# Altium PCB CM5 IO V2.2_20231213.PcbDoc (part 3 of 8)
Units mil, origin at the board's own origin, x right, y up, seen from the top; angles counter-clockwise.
Board outline 6299.61 x 3544.09 mil, 4 copper layers (Top, GND, Power, Bottom), stack 35.4 mil thick; 482 components, 404 nets, 1857 pads, 2731 vias.
Unrouted connection lines stored in the file: 1872.
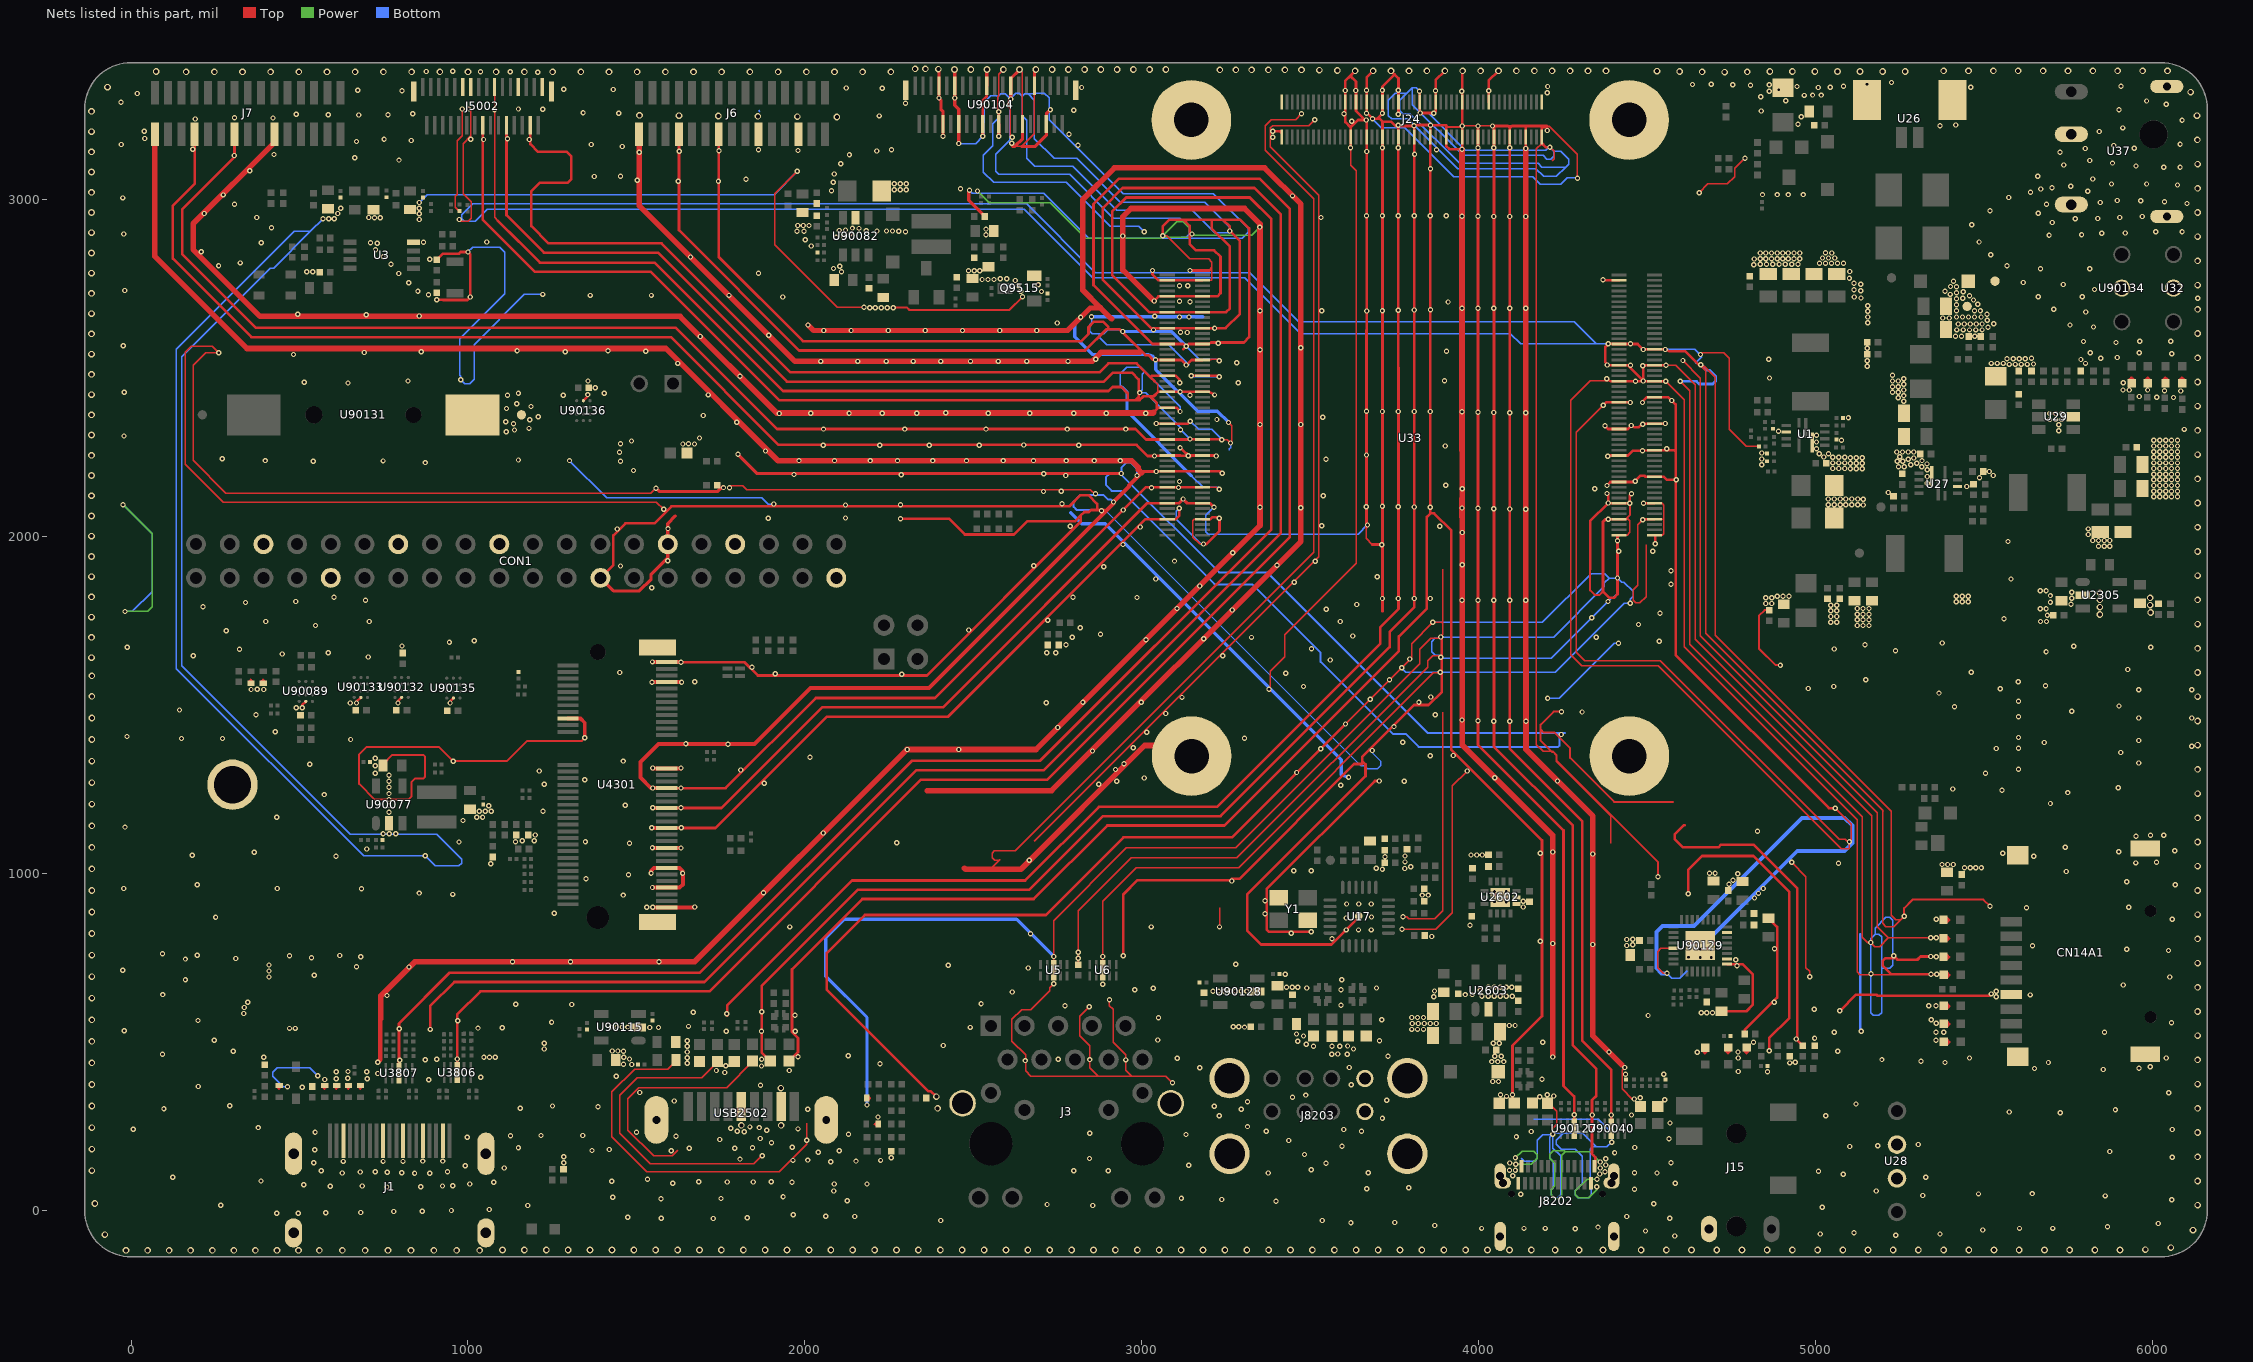
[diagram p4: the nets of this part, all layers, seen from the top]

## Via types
v1: diameter 15.75, hole 7.87, Top to Bottom, 2292 vias
v2: diameter 19.68, hole 11.81, Top to Bottom, 439 vias

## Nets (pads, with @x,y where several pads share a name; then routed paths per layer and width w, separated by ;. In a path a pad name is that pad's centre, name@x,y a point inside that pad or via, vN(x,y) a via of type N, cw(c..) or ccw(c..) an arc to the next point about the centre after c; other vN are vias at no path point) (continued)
GND: C1.2 C3.1 C4.2 C5.2 C34.2 C83.1 C84.2 C85.2 C87.2 C88.2 C89.2 C126.1 C127.1 C130.2 C131.2 C132.2 C133.2 C134.2 C135.2 C136.2 C137.2 C138.2 C139.2 C140.2 C141.2 C142.2 C143.2 C144.2 C146.2 C147.2 C149.2 C150.2 C151.1 C152.2 C153.2 C154.2 C155.2 C156.2 C265.2 C267.2 C268.2 C269.2 C548.2 C549.2 C558.2 C559.2 C561.2 C562.2 C563.2 C564.2 C565.2 C569.2 C570.2 C571.2 C572.2 C573.2 C574.2 C658.2 C750.1 C812.2 C813.2 C2282.2 C2283.2 C2284.2 C2330.2 C2332.2 C2335.2 C2606.2 C2607.2 C2608.2 C2609.2 C2611.2 C2612.2 C2613.2 C2614.2 C7320.2 C7322.2 C90084.2 C90399.2 C90408.2 C90409.2 C90410.2 C90431.2 C90448.2 C90478.2 C90479.2 C90480.2 C90482.2 C90483.2 C90484.2 C90485.2 C90486.2 C90487.2 C90488.2 C90490.2 C90582.1 C90615.2 C90616.2 C90617.2 C90618.1 C90750.2 C90751.2 C90772.2 C90773.2 C90774.2 C90775.2 C90776.2 C90777.2 C90778.2 C90779.2 C90780.2 C90781.2 C90782.1 C90783.1 C90784.1 C90787.1 C90788.1 C90789.2 C90790.2 CN14A1.6 CN14A1.10 CN14A1.11 CN14A1.12 CN14A1.13 CON1.6 CON1.9 CON1.14 CON1.20 CON1.25 CON1.30 CON1.34 CON1.39 D3.1 D4.1 D41.1 D47.1 D48.1 D49.1 D90031.2 D90032.2 D90033.2 D90034.2 D90035.2 D90037.2 ED1.2 ED2.2 ED3.2 ED5.2 ED6.2 ED9.2 ED10.2 ED11.2 ED12.2 ED13.2 ED14.2 ED15.2 ED20.2 ED21.2 ED22.2 ED2109.2 ED2110.2 ED2111.2 ED4806.2 ED7104.2 ED9203.2 ED9204.2 ED9205.2 ED9206.2 ESD2701.2 ESD2702.2 ESD2703.2 ESD2704.2 ESD2706.2 ESD27052.2 J1.2 J1.5 J1.8 J1.11 J1.17 J1.20 J1.21 J1.22 J1.23 J2.1 J3.19 J3.20 J6.3 J6.6 J6.9 J6.12 J6.15 J7.6 J7.9 J7.12 J7.15 J15.2 J24.1 J24.2 J24.7 J24.13 J24.19 J24.22 J24.25 J24.31 J24.32 J24.37 J24.42 J24.43 J24.48 J24.49 J24.55 J24.56 J24.61 J24.62 J24.67 J24.68 J24.72 J24.73 J24.76 J24.99 J24.100 J5002.1 J5002.4 J5002.7 J5002.10 J5002.13 J5002.16 J5002.19 J5002.21 J5002.32 J5002.33 J8202.A1 J8202.A12 J8202.B1 J8202.B12 J8202.E1 J8202.E2 J8202.E3 J8202.E4 J8202.E5 J8202.E6 J8203.4 J8203.8 J8203.9 J8203.10 J8203.11 J8203.12 P6.1 Q9515.2 R1.1 R7.1 R97.1 R102.2 R152.1 R154.1 R160.2 R161.2 R353.2 R2005.2 R2006.2 R2322.2 R2611.2 R2612.2 R5004.2 R7125.2 R7315.1 R90338.1 R91193.2 R95043.2 R95114.1 R95116.2 R95117.2 R95159.2 R95210.2 R95555.2 R95556.2 R95578.1 R95579.2 R95598.2 R95602.2 R95606.1 R95614.2 R95615.2 TP11.1 TP14.1 U1.2 U1.10 U3.4 U5.3 U5.8 U6.3 U6.8 U17.25 U26.3 U26.4 U27.2 U27.10 U28.2 U28.3 U29.2 U32.2 U33.1 U33.2 U33.7 U33.8 U33.13 U33.14 U33.22 U33.23 U33.32 U33.33 U33.42 U33.43 U33.52 U33.53 U33.59 U33.60 U33.65 U33.66 U33.71 U33.74 U33.98 U33.107 U33.108 U33.113 U33.114 U33.119 U33.120 U33.125 U33.126 U33.131 U33.132 U33.137 U33.138 U33.144 U33.150 U33.155 U33.156 U33.161 U33.162 U33.167 U33.168 U33.173 U33.174 U33.179 U33.180 U33.185 U33.186 U33.191 U33.192 U33.197 U33.198 U33.201 U33.202 U33.203 U33.204 U37.2 U37.3 U37.4 U37.5 U2305.2 U2602.8 U2602.9 U2602.15 U2603.2 U3806.3 U3806.8 U3807.3 U3807.8 U4301.1 U4301.7 U4301.18 U4301.33 U4301.39 U4301.45 U4301.51 U4301.57 U4301.63 U4301.69 U4301.75 U4301.76 U4301.77 U90040.3 U90040.8 U90077.2 U90082.2 U90089.D2 U90104.6 U90104.9 U90104.12 U90104.15 U90104.18 U90104.21 U90104.22 U90104.28 U90104.29 U90104.32 U90104.33 U90104.40 U90104.41 U90115.2 U90127.3 U90127.8 U90128.2 U90129.5 U90129.17 U90129.18 U90129.23 U90129.33 U90131.2 U90132.D2 U90133.D2 U90134.2 U90135.D2 U90136.D2 USB2502.4 USB2502.7 USB2502.10 USB2502.11 Y1.2 Y1.4 | length 218612.2
  Top w3.94: v1(974.41,2939.96) 980.31,2934.06 1000.79,2934.06 1009.84,2943.11 1009.84,2992.13 985.24,3016.73 985.24,3165.05 1008.78,3188.59 1008.78,3191.93 1008.78,3261.89 v1(1002.95,3267.72) ; C750.1@974.41,2964.57 966.54,2972.44 966.06,2972.44 962.6,2975.9 962.6,3008.85 968.51,3014.76 968.51,3174.22 983.35,3189.06 983.35,3252.59 983.27,3252.67 v1(983.27,3267.72) ; J5002.13@1078.74,3332.68 1078.74,2945.86 1088.58,2936.02 ; v1(1557.85,2142.26) 1542.56,2126.97 281.8,2126.97 184.06,2224.72 184.06,2506.89 221.93,2544.76 v1(259.97,2544.76) 241.74,2562.99 178.23,2562.99 160.43,2545.19 160.43,2214.26 273.31,2101.38 1559.06,2101.38 v1(1580.71,2079.72) ; C2283.2@1617.13,445.87 1617.13,441.93 1593.5,418.31 1494.77,418.31 1427.17,350.7 1427.17,218.2 1531.19,114.17 1923.54,114.17 2004.92,195.56 2004.92,257.87 ; 1622.05,177.17 1606.3,161.42 1550.76,161.42 1474.41,237.76 1474.41,331.13 1506.47,363.19 1767.66,363.19 1845.74,441.27 1844.49,441.27 D90037.2@1844.49,442.52 ; D90033.2@1740.16,441.54 1740.16,440.29 1741.41,440.29 1693.84,392.72 1502.59,392.72 1450.79,340.92 1450.79,227.98 1540.97,137.8 1847.44,137.8 v1@1875.98,166.34 ; v1(1775.99,2143.51) 1778.54,2149.61 1815.88,2149.61 1826.9,2138.58 2846.65,2138.58 2860.73,2124.51 v1(2862.2,2125.98) ; v1(1977.36,3082.68) 1910.43,3015.75 1910.43,2865.02 2096.32,2679.13 v1(2175.2,2679.13) ; 2473.47,1014.89 2552.74,1014.89 2578.42,1040.57 2578.42,1041.54 ; 2574.61,1038.39 2563.19,1038.39 2555.12,1046.46 2555.12,1059.37 2561.85,1066.1 2623.36,1066.1 3509.25,1952 3509.25,3000.93 3365.16,3145.02 3365.16,3218.14 3383.24,3236.22 3455.71,3236.22 v1(3473.43,3253.94) ; v1(2574.8,3259.84) 2571.85,3269.68 2571.85,3304.13 2574.8,3307.09 2574.8,3371.06 v2(2588.58,3384.84) ; v1(2610.24,3297.24) 2603.35,3290.35 2603.35,3274.61 2609.33,3268.62 2609.33,3183.13 2609.25,3182.99 2613.29,3180.73 v1(2615.16,3184.06) ; 2623.03,3156.5 2642.71,3156.5 2681.1,3194.89 U90104.9@2681.1,3336.61 ; v2(2636.81,3384.84) 2644.76,3376.09 2644.76,3302.25 2644.69,3302.17 2644.69,3224.42 U90104.12@2645.67,3223.43 ; 2680.13,1094.19 3525,1939.06 3525,3011.81 3380.91,3155.91 3380.91,3211.61 3387.8,3218.5 3495.08,3218.5 v1(3512.8,3236.22) ; v1(2738.19,672.24) 2725.85,659.91 2725.85,650.74 2670.58,595.47 2642.72,595.47 2613.19,565.94 2613.19,501.97 2654.53,460.63 2654.53,413.39 2670.28,397.64 2870.08,397.64 ; U5.8@2738.4,727.62 2738.4,859.25 2953.95,1074.8 3277.85,1074.8 3824.32,1621.28 3824.32,1665 3857.22,1697.9 3884.71,1697.9 3886.81,1700 v1(3886.81,1700.79) 3885.33,1702.26 3892.72,1709.65 3892.72,1741.14 ; C3.1@2811.23,728.11 2811.23,888.78 2967.73,1045.28 3281.73,1045.28 3847.94,1611.49 3847.94,1630.06 3863.55,1645.67 3881.89,1645.67 v1(3886.81,1640.75) ; v1(2843.5,603.35) 2815.49,575.33 2815.49,517.44 2845.47,487.45 2845.47,422.24 2870.08,397.64 ; U6.8@2884.07,727.62 2884.07,917.36 2983.44,1016.73 3286.59,1016.73 3864.35,1594.49 3882.87,1594.49 v1(3884.84,1596.46) ; v1(2903.54,624.02) 2903.54,606.45 2914.37,595.63 2914.37,499.02 2951.77,461.61 2951.77,415.35 2969.49,397.64 ; 3037.15,2460.04 3046.26,2450.93 3046.26,2432.09 3049.8,2428.54 ; v1(3062.01,2891.73) 3073.32,2891.73 3142.21,2822.83 3197.52,2822.83 3207.48,2812.88 3207.48,2796.46 ; v1(3090.55,377.95) 3070.87,397.64 2969.49,397.64 ; v1(3142.72,2288.39) 3179.13,2288.39 U33.137@3179.13,2286.81 3252.56,2286.81 v1(3262.8,2276.57) 3266.73,2280.51 3266.73,2327.76 v1(3256.89,2337.6) ; U33.107@3179.13,2050.59 3155.51,2050.59 3150.79,2045.87 3150.79,1996.96 3170.81,1976.94 v1(3182.48,1976.94) ; U33.119@3179.13,2145.08 3179.13,2144.68 3220.33,2144.68 v1(3229.33,2139.76) ; U33.167@3179.13,2523.03 3203.58,2523.03 3206.14,2525.59 3224.41,2525.59 v1(3229.33,2520.67) ; U33.197@3179.13,2759.25 3205.71,2759.25 3207.48,2761.02 3207.48,2792.52 3205.71,2794.29 ; v1(3230.31,840.55) 3230.31,896.91 ; 3380.18,1538.52 3380.18,1599.53 3423.23,1642.58 3423.23,1707.68 3635.83,1920.28 3635.83,3084.65 3619.09,3101.38 v1(3619.09,3152.56) ; v1(3604.05,1442.82) 3800.7,1639.46 3800.7,1681.6 v1(3863.37,1744.28) ; v1@3666.34,2026.57 3665.35,2025.59 3665.35,1993.48 3683.44,1975.39 ; v1(3771.65,833.66) 3872.06,833.66 3921.26,882.86 3921.26,1258.86 v1(3965.55,1303.15) ; v1(3774.61,871.06) 3786.42,871.06 3792.33,865.16 3869.48,865.16 3892.72,888.4 3892.72,1477.36 ; v1(3823.82,3320.87) 3823.82,3320.08 v1@3824.21,3320.08 ; v1@3869.82,1744.09 3889.76,1744.09 3892.72,1741.14 ; 3892.72,1901.57 3892.72,1741.14 ; v1(3950.79,3217.52) v1(4040.35,3217.52) ; 4085.43,3217.52 4098.43,3217.52 ; ESD2703.2@4203.74,317.32 4207.34,317.32 4231.3,293.36 4231.3,254.3 4219.49,242.49 v1(4219.49,225.39) ; v1(4210.63,3154.53) 4223.43,3141.73 4223.43,3119.68 4217.72,3113.98 ; v1(4292.32,3062.01) 4292.32,3133.18 4209.36,3216.14 4186.42,3216.14 4186.42,3213.58 4186.42,3165.35 4170.67,3149.61 4170.67,1380.91 4190.35,1361.22 4215,1361.22 4218.5,1361.22 4229.49,1350.24 4229.49,1332.83 4391.73,1170.58 4391.73,1088.58 ; 4383.45,2397.05 4377.95,2397.05 4288.78,2307.87 4288.78,1655.51 4313.39,1630.91 4538.33,1630.91 5068.84,1100.39 5086.42,1100.39 v1@5095.27,1091.54 ; U33.2@4415.75,2003.35 4439.96,2003.35 4447.83,2011.22 4447.83,2045.28 4442.52,2050.59 U33.8@4415.75,2050.59 ; U33.60@4415.75,2460.04 4415.75,2460.63 4330.12,2460.63 4273.03,2403.54 4273.03,1647.64 4305.51,1615.16 4531.8,1615.16 5075.11,1071.85 5098.43,1071.85 5098.43,1088.38 v1@5095.27,1091.54 ; v1(4433.07,423.23) 4425.2,415.35 4425.2,359.76 4455.23,329.72 v1(4460.63,329.72) ; v1(4486.22,2049.21) 4471.46,2034.45 4471.46,1854.42 4457.68,1840.64 4457.68,1810.24 4465.75,1802.17 4477.16,1802.17 4496.06,1821.06 4496.06,1974.41 ; U33.1@4520.47,2003.35 4544.29,2003.35 4548.82,2007.87 4548.82,2051.18 ; U33.7@4520.47,2050.59 4548.23,2050.59 4548.82,2051.18 ; U33.13@4520.47,2097.83 4543.5,2097.83 4548.82,2092.52 4548.82,2051.18 ; v1(4554.13,2459.65) 4609.25,2404.53 4609.25,1671.37 5122.05,1158.58 5122.05,707 5130.23,698.82 ED12.2@5379.53,698.82 ; v1(4555.12,2506.89) 4584.65,2506.89 4641.73,2449.8 4641.73,1693.9 5165.35,1170.28 5165.35,797.24 v1(5162.4,794.29) ; v1(4558.07,702.76) 4547.44,702.76 4530.51,719.69 4530.51,767.52 4540.18,777.19 U90129.5@4576.96,777.19 ; v1(4597.44,2459.65) 4625,2432.09 4625,1680.12 5137.8,1167.32 5137.8,810.24 5153.74,794.29 v1(5162.4,794.29) ; v1(4605.31,2521.65) 4657.48,2469.49 4657.48,1704.23 5182.09,1179.63 5182.09,841.23 5215.24,808.07 ; v1(4653.54,3019.68) 4679.13,3045.28 4737.2,3045.28 4758.86,3066.93 4758.86,3092.01 4772.62,3105.77 4773.09,3105.77 v1(4789.37,3122.05) ; v1@4656.5,2507.87 4673.23,2491.14 4673.23,1711.92 5199.8,1185.35 5197.83,1183.38 5197.83,851.58 5207.88,841.54 5231.3,841.54 5251.97,862.2 ; v1(4657.48,2539.37) 4662.4,2544.29 4726.38,2544.29 4742.72,2527.95 4742.72,2316.78 4792.76,2266.73 R95116.2@4830.71,2266.73 ; v1(4658.46,2508.86) 4662.4,2504.92 4669.29,2504.92 4701.77,2472.44 4701.77,1705.71 5223.43,1184.06 5223.43,875.2 5236.42,862.2 5251.97,862.2 ; v1(4928.15,1032.48) 4970.47,990.16 4970.47,719.83 4981.3,709 v1(4981.3,692.91) ; v1(5057.09,1192.91) 5104.33,1145.67 5104.33,1100.59 v1@5095.27,1091.54 ; v1(5261.81,872.05) 5251.97,862.2 ; v1(5340.55,808.07) 5215.24,808.07 ; ED14.2@5368.13,817.5 ED14.2@5378.54,807.09 ; 2870.08,397.64 2969.49,397.64 ; v1(5162.4,794.29) 5175.04,781.65 5188.82,781.65 5215.24,808.07
  Top w5.91: C265.2@747.99,1319.87 747.99,1323.81 775.56,1351.38 866.69,1351.38 873.03,1345.04 873.03,1286.85 866.69,1280.51 842.52,1280.51 831.69,1269.68 831.69,1227.36 822.83,1218.5 v1(765.75,1218.5) 723.41,1218.5 677.13,1264.79 677.13,1352.87 699.45,1375.2 912.99,1375.2 v1(955.91,1332.28) 1114.76,1332.28 1175.2,1392.72 1337.6,1392.72 v1(1346.46,1401.57) ; v1(2261.81,2678.15) 2303.28,2678.15 2310.17,2671.26 2606.3,2671.26 v1(2645.67,2710.63) ; 3902.95,3219.49 3907.87,3214.57 3950.79,3214.57 v1(3950.79,3217.52) ; v1(4245.08,1479.33) 4221.42,1479.33 4183.07,1440.99 4183.07,1427.12 ; 4330.12,1901.57 4329.72,1901.18 4329.72,1839.57 4343.5,1825.79 4357.9,1825.79 4368.11,1836 ; U33.8@4415.75,2050.59 4415.75,2049.66 4435.19,2049.66 4447.83,2062.3 v1(4447.83,2097.44) ; v1(4531.5,989.17) 4531.5,1032.21 4230.31,1333.39 4230.31,1350.6 4221.67,1359.25 4216.97,1359.25 4215,1361.22 4183.07,1393.15 4183.07,1427.12 ; 4575.79,1211.61 4401.03,1211.61 4270.67,1341.97 4270.67,1371.06 4224.41,1417.32 4192.87,1417.32 4183.07,1427.12 ; C131.2@4861.22,1780.51 4847.88,1780.51 4830.71,1763.34 4830.71,1666.73 4880.31,1617.13 v1(4894.69,1617.13) ; v1(5261.81,872.05) 5261.81,896.39 5286.69,921.26 5497.05,921.26 v1(5516.73,901.57)
  Top w7.87: J7.12@188.98,3192.91 188.98,3045.86 124.02,2980.9 124.02,2823.82 357.28,2590.55 1602.36,2590.55 1921.85,2271.06 2984.25,2271.06 3017.13,2238.19 v1(3037.4,2238.19) 3056.69,2239.57 U33.132@3075.2,2239.57 3113.58,2239.57 3113.98,2239.17 v1(3137.8,2239.17) ; J7.9@307.09,3192.91 307.09,3125 151.57,2969.49 151.57,2837.6 370.08,2619.09 1616.14,2619.09 1916.93,2318.31 2980.91,2318.31 3012.4,2286.81 U33.138@3075.2,2286.81 3141.14,2286.81 v1(3142.72,2288.39) 3160.63,2286.81 U33.137@3179.13,2286.81 3179.72,2287.4 3236.22,2287.4 v1(3237.2,2286.42) ; v1(507.87,1491.14) 507.87,1499.01 U90089.D2@518.71,1509.84 ; v1(669.29,1504.92) 669.29,1508.85 U90133.D2@682.09,1521.65 ; v1(792.32,1504.92) 792.32,1510.82 U90132.D2@803.15,1521.65 ; U3807.3@795.28,421.76 795.28,554.13 945.87,704.72 1687.99,704.72 2316.93,1333.66 2697.37,1333.66 3383.86,2020.15 3383.86,2940.94 3319.88,3004.92 2953.4,3004.92 2911.42,2962.94 2911.42,2774.61 3021.26,2664.76 U33.186@3075.2,2664.76 U33.185@3179.13,2664.76 3249.41,2664.76 3260.83,2676.18 3260.83,2859.25 3206.69,2913.39 3206.69,2938.98 ; v1(887.8,536.42) 887.8,605.31 959.65,677.17 1701.77,677.17 2329.72,1305.12 2707.88,1305.12 3411.42,2008.65 3411.42,2955.71 3333.66,3033.46 2942.97,3033.46 2883.86,2974.36 2883.86,2760.83 3027.17,2617.52 ; v1(907.48,2701.77) 925.53,2701.77 926.52,2700.79 998.03,2700.79 v1(1006.89,2709.65) 1006.89,2836.61 v1(1000,2843.5) 978.5,2843.5 973.58,2838.58 925.2,2838.58 C90616.2@907.48,2820.87 ; v1(946.85,1504.92) 946.85,1509.83 U90135.D2@956.7,1519.68 ; U3806.8@968.5,423.72 968.5,581.69 1036.42,649.61 1716.54,649.61 2344.49,1277.56 2719.32,1277.56 3438.98,1997.21 3438.98,2970.47 3348.43,3061.02 2931.55,3061.02 2856.3,2985.77 2856.3,2745.08 3031.1,2570.28 U33.174@3075.2,2570.28 3121.49,2570.28 v1(3131.89,2563.98) ; J5002.16@1043.3,3219.5 1043.3,2939.96 1198.81,2784.45 1542.54,2784.45 1923.45,2403.54 2957.68,2403.54 ; 1088.58,2936.02 1150.59,2874.02 1151.57,2874.02 1213.58,2812.01 1553.96,2812.01 1934.86,2431.1 2900.59,2431.1 2912.4,2442.91 2938.98,2442.91 2957.68,2424.21 2957.68,2403.54 ; J5002.10@1114.17,3219.5 1114.17,2952.76 1225.39,2841.54 1563.4,2841.54 1946.28,2458.66 2886.81,2458.66 2913.39,2485.24 2970.11,2485.24 2990.16,2465.18 2990.16,2412.4 2981.3,2403.54 ; v1(1182.09,3177.17) v1@1185.04,3177.17 ; J5002.4@1185.04,3219.5 v1@1185.04,3177.17 ; U90136.D2@1342.27,2402.14 1355.31,2415.19 v1(1355.31,2420.28) ; CON1.25@1392.94,1876.36 1431.5,1914.92 1431.5,2002.76 1466.93,2038.19 1552.83,2038.19 1603.22,2088.58 2784.25,2088.58 2817.32,2121.65 2840.94,2121.65 2867.13,2095.47 2867.13,2077.76 ; U4301.51@1589.78,1134.21 1734.61,1134.21 2064.96,1464.57 2425.2,1464.57 3011.22,2050.59 U33.108@3075.2,2050.59 3100.39,2050.59 3110.24,2060.43 v1(3110.24,2082.68) ; U4301.45@1589.78,1193.27 1751.97,1193.27 2050.83,1492.13 2409.06,1492.13 3014.76,2097.83 U33.114@3075.2,2097.83 3109.65,2097.83 v1(3122.05,2110.24) 3134.45,2097.83 U33.113@3179.13,2097.83 3201.38,2097.83 v1(3213.58,2085.63) ; U4301.39@1589.78,1252.32 1764.76,1252.32 2032.13,1519.68 2385.83,1519.68 3011.22,2145.08 U33.120@3075.2,2145.08 3093.7,2145.08 v1(3108.27,2144.68) 3108.66,2145.08 U33.119@3179.13,2145.08 ; J6.12@1625.98,3192.91 1625.98,2908.13 1982.93,2551.18 2831.55,2551.18 2894.55,2614.17 2899.61,2614.17 ; v1(1631.89,1625.98) 1820.87,1625.98 1860.24,1586.61 2362.06,1586.61 2818.34,2042.88 2818.34,2061.08 ; J6.9@1744.09,3192.91 1744.09,2828.99 1994.34,2578.74 2820.14,2578.74 2841.54,2600.14 2841.54,2620.08 2858.27,2636.81 2884.48,2636.81 2899.61,2621.68 2899.61,2614.17 ; v1@1769.69,576.77 1769.69,608.27 2139.76,978.35 2653.51,978.35 2872.22,1197.05 3222.17,1197.05 3707.36,1682.24 3707.36,1730 3761.22,1783.86 3761.22,2500.07 3760.83,2500.46 v1@3760.83,3217.52 ; D90032.2@1896.65,442.52 1872.13,467.04 1872.13,666.34 2156.58,950.79 2665.1,950.79 2883.73,1169.41 3233.5,1169.41 3734.92,1670.83 3734.92,1716.22 3808.46,1789.76 3808.46,3216.14 v1@3808.07,3216.54 ; D90031.2@1952.76,442.52 1979.33,469.09 1979.33,510.83 1961.61,528.54 1961.61,714.57 2170.28,923.23 2678.84,923.23 2897.34,1141.73 3244.8,1141.73 3762.48,1659.41 3762.48,1702.44 3845.49,1785.45 3845.49,2057.7 3855.71,2067.91 ; v1(2283.46,2052.17) 2427.17,2052.17 2474.41,2004.92 2620.08,2004.92 2659.45,2044.29 2801.55,2044.29 2818.34,2061.08 ; v2(2389.76,336.61) 2373.08,353.3 2365.43,353.3 2064.96,653.77 2064.96,763.24 2177.7,875.98 2714.64,875.98 2944.95,1106.3 3267.53,1106.3 v1(3604.05,1442.82) ; U90104.22@2527.56,3223.43 2527.56,3292.87 2539.37,3304.68 U90104.21@2539.37,3336.61 ; U90104.18@2574.8,3223.43 v1(2574.8,3259.84) ; 2891.73,2073.37 2887.35,2077.76 2867.13,2077.76 ; v1(2944.49,755.12) 2944.49,936.61 2987.05,979.17 3260.78,979.17 v1@3264.73,975.23 ; 2999.02,2187.99 2999.02,2191.93 v1(3042.32,2191.93) 3056.69,2192.32 U33.126@3075.2,2192.32 U33.125@3179.13,2192.32 3230.91,2192.32 3233.27,2189.96 v1(3238.19,2187.01) ; v1@3031.5,2790.75 v1(3031.5,2788.39) 3031.5,2776.57 3048.82,2759.25 U33.198@3075.2,2759.25 U33.197@3179.13,2759.25 ; 3034.45,2367.13 3044.29,2376.97 ; v1(3034.45,2612.2) 3032.48,2612.2 3027.17,2617.52 ; v1(3036.42,2697.83) 3035.53,2698.72 3048.82,2712.01 U33.192@3075.2,2712.01 U33.191@3179.13,2712.01 3223.82,2712.01 3233.27,2721.46 3233.27,2829.36 3214.2,2848.43 3160.43,2848.43 3141.73,2867.13 3141.73,2921.26 3124.02,2938.98 ; 3037.15,2460.04 3025.59,2471.6 ; v1(3042.32,2334.65) 3056.69,2334.06 U33.144@3075.2,2334.06 3136.22,2334.06 v1(3143.7,2341.54) ; v1(3062.01,2891.73) 3062.01,2920.14 3080.85,2938.98 3124.02,2938.98 ; v1(3112.2,2455.71) 3112.2,2463.98 3100.39,2475.79 U33.162@3075.2,2475.79 3029.78,2475.79 3025.59,2471.6 ; v1(3113.19,2262.8) 3130.65,2245.33 3133.6,2245.33 v1@3142.72,2236.22 ; v1(3113.19,2370.08) 3101.97,2381.3 U33.150@3075.2,2381.3 3048.62,2381.3 3044.29,2376.97 ; 3122.44,2554.53 v1(3131.89,2563.98) ; v1@3131.89,2507.28 v1(3131.89,2507.87) ; v1@3132.48,2507.28 v1(3131.89,2507.87) ; v1@3141.73,2235.24 v1(3137.8,2239.17) ; v1(3142.72,2788.39) 3199.8,2788.39 3205.71,2794.29 ; v1(3146.65,2476.38) 3150.12,2475.79 U33.161@3179.13,2475.79 3229.33,2475.79 v1(3229.33,2473.43) ; U33.107@3179.13,2050.59 3202.93,2050.59 3208.44,2056.1 3229.33,2056.1 v1(3229.33,2053.15) 3230.31,2053.15 3230.31,2015.96 3191.3,1976.94 v1(3182.48,1976.94) ; U33.167@3179.13,2523.03 3147.05,2523.03 v1(3131.89,2507.87) ; v1(3215.55,2419.29) 3197.64,2428.54 U33.155@3179.13,2428.54 3113.78,2428.54 v1(3113.19,2429.13) 3093.7,2428.54 U33.156@3075.2,2428.54 3049.8,2428.54 3048.23,2428.54 3035.04,2415.35 3024.24,2415.35 ; v1(3220.47,2238.19) 3220.47,2239.57 U33.131@3179.13,2239.57 3137.8,2239.57 v1(3137.8,2239.17) ; v1(3266.2,976.86) 3266.2,983.27 3289.37,983.27 3629.92,1323.82 3652.56,1323.82 3653.54,1324.8 3653.54,1332.68 ; v1(3387.8,3201.77) 3409.45,3201.77 J24.99@3413.39,3197.83 ; v1(3501.97,825.79) 3377.67,825.79 3370.09,833.37 3370.09,952.77 3690.94,1273.62 v1(3703.74,1273.62) ; v1(3619.09,3152.56) 3619.49,3166.14 J24.73@3619.49,3184.65 3619.49,3213.58 ; v2@3635.24,3378.54 v2(3632.87,3380.91) 3618.11,3366.14 ; U17.25@3643.25,872.81 3644.87,871.36 3561.9,788.39 3353.21,788.39 3312.01,829.58 3312.01,936.52 3663.39,1287.89 3663.39,1322.83 3653.54,1332.68 ; v1@3666.34,2026.57 3666.34,2611.42 3666.73,2611.81 3666.73,3235.24 v1(3665.35,3235.24) v1@3662.2,3235.24 ; 3683.44,1975.39 v1@3713.98,1975.39 ; v2(3686.02,3380.91) 3666.73,3361.61 J24.68@3666.73,3288.58 3666.73,3257.48 3684.06,3240.16 v1(3684.06,3239.17) 3698.82,3239.17 ; v1(3711.61,1974.41) v1@3713.98,1975.39 ; 3713.98,1777.19 v1@3713.98,1975.39 ; v2(3739.17,3380.91) 3750,3370.08 ; v1(3760.83,3219.49) v1@3760.83,3217.52 ; v1(3760.83,3251.97) 3761.22,3252.36 3761.22,3358.86 3750,3370.08 ; v1(3807.09,3218.5) v1@3808.07,3216.54 ; v1@3824.21,3320.08 3824.21,3320.87 v1(3823.82,3320.87) 3824.21,3318.9 J24.48@3824.21,3288.58 3824.21,3259.23 v1(3825.79,3255.91) 3865.55,3255.91 3871.46,3261.81 J24.42@3871.46,3288.58 3871.46,3353.74 v2(3898.62,3380.91) ; v1(3886.81,1700.79) 3889.76,1697.83 3889.76,1538.39 3850.39,1499.02 3807.31,1499.02 3653.54,1345.25 3653.54,1332.68 ; J24.37@3902.95,3182.68 3902.95,3219.49 v1(3856.3,3219.49) v1@3855.71,3220.08 ; J24.37@3902.95,3184.65 3902.95,3158.46 3912.8,3148.62 v1(3949.8,3148.62) 3950.2,3149.02 J24.31@3950.2,3184.65 ; J24.31@3950.2,3184.45 3950.2,3208.66 ; v1(3950.79,3217.52) 3950.2,3218.11 J24.32@3950.2,3288.58 3950.2,3379.33 v2(3951.77,3380.91) ; v1(3997.05,3217.52) 3997.44,3217.13 3997.44,1380.91 4250.98,1127.36 4250.98,369.09 4282.49,337.59 U90127.8@4282.49,257.37 ; J24.22@4028.94,3288.58 4028.94,3351.77 v2(4058.07,3380.91) ; ESD2706.2@4104.57,317.65 4099.41,322.81 4099.41,487.99 4187.2,575.79 4187.2,1097.24 3918.31,1366.14 3918.31,2016.37 3866.76,2067.91 3855.71,2067.91 ; v1(4138.78,3150.59) 4139.17,3150.98 J24.7@4139.17,3184.65 4139.17,3217.52 ; v1(4202.76,3203.74) 4202.76,3213.58 ; v1(4210.63,3154.53) 4198.03,3154.53 4186.42,3166.14 J24.1@4186.42,3184.65 4186.42,3213.58 4202.76,3213.58 ; 4330.12,1901.57 4330.12,2044.68 v1(4383.86,2098.43) ; J8202.A12@4343.06,130.51 4344.69,130.51 4344.69,158.26 4335.63,167.32 4335.63,326.77 4348.43,339.57 4348.43,419.29 4278.54,489.17 4278.54,1141.14 4044.69,1375 4044.69,3213.19 v1(4040.35,3217.52) 4085.43,3217.52 4091.93,3211.02 ; v1(4368.11,2760.83) 4369.09,2759.84 4387.67,2759.84 4388.26,2759.25 U33.98@4415.75,2759.25 ; v1(4369.09,2388.78) 4377.45,2397.13 4383.37,2397.13 4383.45,2397.05 U33.52@4415.75,2397.05 4434.25,2397.05 v1(4448.82,2396.65) ; v1(4374.02,2327.76) 4383.46,2318.31 U33.42@4415.75,2318.31 4442.13,2318.31 4452.17,2328.35 v1(4451.77,2328.74) 4460.63,2323.82 4474.44,2323.82 4484.76,2334.14 v1(4486.22,2332.68) 4487.86,2334.06 U33.43@4520.47,2334.06 4549.64,2334.06 v1(4553.15,2334.65) ; v1(4378.94,2467.52) 4383.49,2462.97 4390.75,2460.04 U33.60@4415.75,2460.04 4443.72,2460.04 4444.12,2459.65 4487.2,2459.65 v1(4487.2,2460.63) ; v1(4379.92,2150.59) 4390.16,2160.83 U33.22@4415.75,2160.83 4463.58,2160.83 v1(4463.58,2163.39) 4463.11,2163.86 4478.38,2179.13 4491.54,2179.13 4494.09,2176.57 U33.23@4520.47,2176.57 4548.23,2176.57 4557.48,2167.32 v1(4585.63,2167.32) ; v1(4381.89,2237.2) 4389.39,2239.57 U33.32@4415.75,2239.57 4442.32,2239.57 4456.69,2253.94 v1(4485.24,2253.94) 4501.97,2255.31 U33.33@4520.47,2255.31 4580.31,2255.31 4583.66,2251.97 ; v1(4383.86,2050.2) 4368.11,2043.67 4368.11,2043.31 ; v1@4383.86,2127.95 v1(4383.86,2098.43) ; U90040.8@4393.1,257.38 4393.1,415.95 4306.1,502.95 4306.1,1154.53 4091.54,1369.09 v1(4091.54,3152.56) 4091.93,3152.95 J24.13@4091.93,3184.65 4091.93,3211.02 ; U33.2@4415.75,2003.35 4411.42,1999.02 v1(4411.42,1986.22) 4411.42,1828.12 4400.22,1816.93 4387.18,1816.93 4368.11,1836 4368.11,2043.31 ; U33.8@4415.75,2050.59 4375.39,2050.59 4368.11,2043.31 ; v1(4447.83,2097.44) 4434.25,2097.83 U33.14@4415.75,2097.83 4397.24,2097.83 v1(4383.86,2098.43) ; v1@4447.83,2099.41 4447.83,2121.06 v1(4452.76,2125.98) ; v1(4485.24,2396.65) 4485.24,2399.32 4498.71,2412.8 U33.53@4520.47,2412.8 4561.61,2412.8 v1(4571.85,2402.56) 4583.66,2390.75 4583.66,2251.97 ; v1(4486.22,2049.21) 4486.22,2050.59 U33.7@4520.47,2050.59 ; v1(4488.19,2097.44) 4501.97,2097.83 U33.13@4520.47,2097.83 ; U33.1@4520.47,2003.35 4523.62,2003.35 v1(4523.62,1977.36) ; v1(4554.13,2459.65) 4554.13,2460.04 U33.59@4520.47,2460.04 4501.97,2460.04 v1(4487.2,2460.63) ; v1(4555.12,2506.89) 4538.98,2507.28 U33.65@4520.47,2507.28 4493.5,2507.28 4487.2,2500.98 v1@4487.2,2462.2 ; 4610.24,1142.72 4608.63,1142.72 4580.71,1114.79 4580.71,1101.74 4605.68,1076.77 4711.12,1076.77 4719,1084.65 4814.87,1084.65 4944.88,954.64 4944.88,503.94 R7315.1@4960.63,488.19 ; v1(4621.06,938.98) 4621.06,1009.81 4662.43,1051.18 4814.93,1051.18 4921.26,944.85 4921.26,570.9 4861.22,510.86 v1(4861.22,473.43) ; v1(4658.46,2508.86) 4657.48,2508.86 4656.5,2507.87 4653.32,2507.87 4611.98,2549.21 4564.93,2549.21 v1(4553.15,2554.13) 4553.15,2554.53 U33.71@4520.47,2554.53 4501.97,2554.53 v1(4487.2,2554.13) 4471.06,2570.28 U33.74@4415.75,2570.28 4397.24,2570.28 v1(4383.86,2570.87) 4375,2562.01 4375,2515.75 4383.46,2507.28 U33.66@4415.75,2507.28 4442.13,2507.28 v1@4487.2,2462.2 ; C569.2@4719.67,590.18 4793.25,590.18 4812.99,609.93 4812.99,699.13 4782.17,729.95 U90129.17@4736.4,729.95 ; C561.2@4788.39,522.64 4788.39,534.45 4884.84,630.91 4884.84,840.55 C565.2@4859.25,866.14 ; v1(5057.09,1192.91) 5038.39,1192.91 4583.66,1647.64 4583.66,2251.97 ; v1(5070.87,591.54) 5119.09,639.76 5179.37,639.76 5183.31,635.83 5514.76,635.83 v1(5520.67,641.73) ; v1(5340.55,752.95) 5310.6,752.95 5300.76,743.11 5242.36,743.11 5237.44,748.03 5207.06,748.03 5197.83,738.81 5197.83,725.76 5223.79,699.8 v1(5341.54,699.8) ; v1@1185.04,3177.17 1185.04,3163.92 1208.21,3140.75 1293.31,3140.75 1306.1,3127.95 1306.1,3059.06 1296.26,3049.21 1213.44,3049.21 1187.99,3023.76 1187.99,2920.27 1239.17,2869.09 1574.82,2869.09 1957.69,2486.22 2873.88,2486.22 2900.45,2512.8 2984.39,2512.8 3025.59,2471.6 ; 2818.34,2061.08 2829.11,2071.85 2842.89,2071.85 2848.79,2077.76 2867.13,2077.76 ; 2899.61,2614.17 2933.8,2614.17 3010.57,2537.4 3019.32,2537.4 3033.1,2523.62 v1(3040.35,2523.62) 3040.85,2524.11 3041.93,2523.03 U33.168@3075.2,2523.03 3116.73,2523.03 v1(3131.89,2507.87) ; 2957.68,2403.54 2981.3,2403.54 ; 2981.3,2403.54 2992.96,2403.54 3004.77,2415.35 3024.24,2415.35 ; 3024.24,2415.35 3044.29,2395.3 3044.29,2376.97 ; 3027.17,2617.52 U33.180@3075.2,2617.52 U33.179@3179.13,2617.52 3248.43,2617.52 3290.35,2659.45 3290.35,2875.98 v1(3260.83,2905.51) 3260.83,2918.92 3240.78,2938.98 ; 3124.02,2938.98 3206.69,2938.98 ; v1(3131.89,2563.98) 3138.19,2570.28 U33.173@3179.13,2570.28 3197.64,2570.28 3205.71,2574.8 3302.17,2574.8 3317.91,2590.55 3317.91,2913.02 3291.96,2938.98 3240.78,2938.98 ; 3206.69,2938.98 3240.78,2938.98 ; 3618.11,3366.14 3635.24,3349.02 J24.72@3635.24,3288.58 3635.24,3262.2 v1@3662.2,3235.24 ; 3618.11,3366.14 3603.74,3351.77 J24.76@3603.74,3288.58 3603.74,3229.33 3619.49,3213.58 ; 3619.49,3213.58 3641.14,3235.24 v1@3662.2,3235.24 ; 3698.82,3239.17 3705.12,3239.17 3713.98,3230.31 ; 3698.82,3239.17 3713.98,3254.33 J24.62@3713.98,3288.58 3713.98,3334.06 3750,3370.08 ; v1@3713.98,1975.39 3713.98,3230.31 ; 3713.98,3230.31 3739.42,3230.31 3752.22,3217.52 v1@3760.83,3217.52 ; v1@3760.83,3217.52 3807.09,3217.52 v1@3808.07,3216.54 ; v1@3808.07,3216.54 3812.01,3220.47 3855.31,3220.47 v1@3855.71,3220.08 ; 3855.71,2067.91 v1@3855.71,3220.08 ; 4091.93,3211.02 4098.43,3217.52 4139.17,3217.52 ; 4139.17,3217.52 4200.79,3217.52 4202.76,3215.55 4202.76,3213.58 ; v1(4487.2,2460.63) v1@4487.2,2462.2
  Top w9.84: CON1.25@1392.94,1876.36 1431.7,1837.6 1508.46,1837.6 1543.31,1872.44 1543.31,1886.65 1592.94,1936.28 CON1.30@1592.94,1976.36 1592.94,2037.27 1615.71,2060.04 ; v1(1557.85,2142.26) 1567.24,2132.87 1741.77,2132.87 1755.8,2146.9 v1(1758.41,2144.29) ; v1(1801.18,2243.11) 1858.27,2186.02 v1(2938.98,2186.02) ; v2(2395.67,3385.83) 2397.61,3385.83 U90104.33@2397.64,3336.61 ; U90104.33@2397.64,3336.61 v1(2397.64,3300.2) 2403.54,3294.29 2403.54,3266.56 2409.45,3260.65 U90104.32@2409.45,3223.43 v1(2409.45,3187.01) ; v2(2443.9,3384.84) 2444.87,3384.84 U90104.29@2444.88,3336.61 ; U90104.29@2444.88,3336.61 v1(2444.88,3300.2) 2444.88,3278.44 2456.69,3266.63 U90104.28@2456.69,3223.43 v1(2456.69,3165.35) ; v1(2488.19,3026.57) 2487.2,3020.67 2486.22,3020.67 2486.22,2996.97 2533.92,2949.28 2533.46,2949.28 C90751.2@2533.46,2948.82 ; v1(2527.56,3187.01) U90104.22@2527.56,3223.43 ; U90104.21@2539.37,3336.61 2539.39,3384.84 v2(2540.35,3384.84) ; v1(2574.8,3187.01) U90104.18@2574.8,3223.43 ; v1(2610.24,3297.24) U90104.15@2610.24,3336.61 2610.24,3358.27 v2(2636.81,3384.84) ; v1(2613.19,3166.34) 2616.14,3157.48 2623.03,3156.5 2645.67,3179.13 U90104.12@2645.67,3223.43 ; 2642.71,3156.5 2683.07,3156.5 2716.54,3189.96 U90104.6@2716.54,3223.43 2716.54,3253.94 v1(2728.35,3265.75) ; U90104.9@2681.1,3336.61 2681.16,3336.61 2681.16,3384.84 v2(2685.04,3384.84)
  Top w11.81: U4301.18@1296.47,1459.01 1333.87,1459.01 1346.46,1446.43 v1(1346.46,1401.57) ; v1(1543.31,1000) 1543.31,1007.03 1552.38,1016.1 U4301.63@1589.78,1016.1 1627.17,1016.1 1636.81,1006.47 v1(1636.81,1000) 1637.8,999.02 1637.8,966.54 1628.31,957.05 U4301.69@1589.78,957.05 1547.24,957.05 v1(1547.24,957.68) ; v1(1545.28,1134.84) 1545.28,1134.21 U4301.51@1589.78,1134.21 ; v1(1546.26,1566.93) 1546.26,1567.28 U4301.7@1589.78,1567.28 1633.86,1567.28 v1(1633.86,1566.93) ; v1(1547.24,1075.79) 1547.24,1075.16 U4301.57@1589.78,1075.16 1631.89,1075.16 v1(1631.89,1074.8) ; v1(1547.24,1626.97) 1547.24,1626.34 U4301.1@1589.78,1626.34 1631.89,1626.34 v1(1631.89,1625.98) ; v1(1548.23,898.62) 1548.23,897.99 U4301.75@1589.78,897.99 1671.61,897.99 v1(1673.23,899.61) ; v1(1548.23,1193.9) 1548.23,1193.27 U4301.45@1589.78,1193.27 ; v1(1548.23,1312.01) 1548.23,1311.38 U4301.33@1589.78,1311.38 1631.89,1311.38 v1(1631.89,1312.01) ; U4301.39@1589.78,1252.32 1548.23,1252.32 v1(1548.23,1252.95) 1542.35,1252.95 1511.81,1283.49 1511.81,1329.7 1564.99,1382.87 1850.14,1382.87 2016.48,1549.21 2367.57,1549.21 2891.73,2073.37 2915.35,2096.99 v1(2915.35,2101.38) 2962.06,2148.08 2962.06,2151.03 2999.02,2187.99
  Top w13.78: v1(732.28,438.98) 739.17,445.87 739.17,565.94 741.14,567.91
  Top w15.75: v1(2008.86,2626.97) 2025.59,2610.24 2779.53,2610.24 2846.46,2677.17 2877.59,2677.17 ; 2992.16,2741.14 3035.47,2697.83 v1(3036.42,2697.83)
  Top w16.54: J7.15@70.87,3192.91 70.87,2830.35 344.13,2557.09 1587.01,2557.09 1920.28,2223.82 2444.29,2223.82 2444.88,2224.41 2969.17,2224.41 2989.17,2204.41 2989.17,2197.83 2999.02,2187.99 ; J7.6@425.2,3192.91 426.12,3192.91 426.12,3168.86 184.45,2927.19 184.45,2850.85 382.74,2652.56 1629.33,2652.56 1916.34,2365.55 3032.87,2365.55 3034.45,2367.13 ; 741.14,567.91 741.14,635.83 842.52,737.2 1672.74,737.2 2302.66,1367.13 2685.64,1367.13 3350.39,2031.88 3350.39,2926.54 3304.49,2972.44 2967.52,2972.44 2943.5,2948.43 2943.5,2789.8 2992.16,2741.14 ; J6.15@1507.87,3192.91 1507.87,2981.14 1970.31,2518.7 2851.87,2518.7 2878.44,2545.28 2994.09,2545.28 ; 2363.19,1245.08 2732.05,1245.08 3471.46,1984.48 3471.46,2985.24 3363.78,3092.91 2918.34,3092.91 2824.41,2998.98 2824.41,2730.35 2877.59,2677.17 2909.76,2645 ; 2473.47,1014.89 2476.94,1011.42 2640.41,1011.42 3007.93,1378.94 U33.202@3147.24,1378.94 ; U33.203@3146.46,3266.73 U33.203@3189.96,3266.73 ; v1(3949.8,3148.62) v1(3949.8,2949.8) v1(3949.8,2676.18) v1(3949.8,2369.09) 3949.8,2255.12 3950.39,2254.53 v1(3950.39,2140.55) 3950.39,2112.4 3949.8,2111.81 v1(3949.8,2083.66) 3949.8,2057.56 3950.39,2056.97 v1(3950.39,2011.02) v1(3950.39,1915.75) 3950.39,1381 4219.09,1112.3 v1@4219.09,457.68 ; v1(4138.78,3150.59) v1(4138.78,2948.82) v1(4138.78,2676.18) v1(4138.78,2366.14) v1(4138.78,2079.72) v1(4138.78,1810.04) 4138.78,1630.91 4139.76,1629.92 v1(4139.76,1450.79) 4139.76,1367.81 4338.09,1169.49 4338.09,517.22 4423.23,432.09
  Power w3.94: v1(-23.62,2093.5) 63.02,2006.86 63.02,1790.38 49.21,1776.57 v1(-17.72,1776.57) ; v1(2511.81,3024.61) 2547.24,2989.17 2728.35,2989.17 2832.68,2884.84 3055.12,2884.84 v1(3062.01,2891.73) ; v1(3349.41,2917.32) 3325.79,2893.7 3151.57,2893.7 v1(3148.62,2896.65) ; v1(4108.27,155.51) 4127.95,175.2 4163.19,175.2 4173.23,165.16 4173.23,153.74 4155.31,135.83 v1(4109.25,135.83) ; 4215.29,149.08 4210.63,153.74 4210.63,166.34 4220.47,176.18 4253.94,176.18 4256.89,173.23 ; 4215.34,149.08 4225.39,139.02 4225.39,71.85 4214.57,61.02 4214.57,45.47 4225.59,34.45 4238.19,34.45 4246.06,42.32 4246.06,162.4 4256.89,173.23 ; v1(4349.41,69.88) 4349.41,61.22 4325.59,37.4 4294.49,37.4 4286.42,45.47 4286.42,56.89 4321.06,91.54 v1(4350.39,91.54) ; v1(4360.24,142.72) 4329.72,173.23 4256.89,173.23 ; v1(3062.01,2891.73) 3103.35,2933.07 3122.83,2933.07 3140.71,2915.19 3140.71,2904.56 v1(3148.62,2896.65) ; v1(3062.01,2891.73) 3062.01,2887.8 3139.76,2887.8 v1(3148.62,2896.65)
  Bottom w3.94: v1(-23.62,2093.5) 63.02,2006.86 63.02,1835.66 3.94,1776.57 v1(-17.72,1776.57) ; v1(464.57,366.14) 451.97,366.14 420.28,397.84 420.28,409.25 433.27,422.24 530.51,422.24 v1(554.13,398.62) ; v1(569.88,2941.93) 532.48,2904.53 ; v1(855.31,2990.16) 878.94,3013.78 1908.46,3013.78 v1(1977.36,3082.68) ; v1(1000,2843.5) 1014.12,2857.62 1093.84,2857.62 1109.25,2842.21 1109.25,2719.8 975.39,2585.94 975.39,2477.36 978.35,2474.41 v1(978.35,2464.57) 990.16,2452.76 1005.71,2452.76 1018.7,2465.75 1018.7,2568.84 1167.38,2717.52 v1(1221.46,2717.52) ; v1(1301.18,2224.41) 1411.02,2114.57 1872.21,2114.57 1891.3,2095.47 v1(1907.48,2095.47) ; 1863.19,3264.32 1866.14,3259.84 ; v1(2456.69,3165.35) 2506.52,3165.35 2527.56,3186.39 v1(2527.56,3187.01) ; v1(2488.19,3026.57) 2497.05,3017.72 2708.66,3017.72 2841.54,2884.84 3298.03,2884.84 3314.96,2901.77 3314.96,2913.19 3211.42,3016.73 2944.21,3016.73 2724.41,3236.53 2724.41,3300.98 2710.43,3314.96 2680.12,3314.96 2678.15,3312.99 ; v1@2531.5,3187.01 2531.5,3287.2 2551.38,3307.09 2568.7,3307.09 2571.85,3303.94 ; v1@2571.85,3264.32 2571.85,3303.94 ; v1(2574.8,3259.84) 2574.8,3242.13 2557.09,3224.41 2557.09,3158.16 2529.53,3130.6 2529.53,3080.71 2560.04,3050.2 2775.4,3050.2 2905.32,2920.28 2990.16,2920.28 v1(3006.89,2903.54) ; v1(2610.24,3297.24) 2594.49,3312.99 2580.91,3312.99 2571.85,3303.94 ; 2684.84,3312.99 2678.15,3312.99 ; v1(2850.39,2651.57) 2850.39,2633.76 2844.49,2627.85 2844.49,2608.47 2852.56,2600.39 2873.03,2600.39 ; 2940.94,2441.97 2935.04,2447.88 2935.04,2482.28 2954.72,2501.97 2995.75,2501.97 3008.86,2488.86 ; v1(2942.91,2607.28) 2937.99,2612.2 2898.62,2612.2 2886.81,2600.39 2873.03,2600.39 ; v1(3110.24,2082.68) 3102.36,2074.8 3102.36,2050.39 3179.15,1973.61 v1(3182.48,1976.94) ; v1(3113.19,2370.08) 3113.19,2384.53 3008.86,2488.86 ; 3116.14,2887.8 3131.69,2887.8 3139.76,2895.87 3139.76,2916.34 3112.2,2943.9 2915.1,2943.9 2785.18,3073.82 2574.44,3073.82 2565.94,3082.31 2565.94,3133.61 2607.28,3174.95 2607.28,3296.06 2625.2,3313.98 2636.61,3313.98 2644.69,3305.9 2644.69,3304.92 ; v1(3131.89,2563.98) 3170.28,2525.59 3220.33,2525.59 v1(3229.33,2520.67) ; 3140.75,2506.89 3079.72,2567.91 2894.88,2567.91 2873.03,2589.76 2873.03,2600.39 ; v1(3142.72,2288.39) 3115.16,2315.94 v1(3114.17,2315.94) 3114.17,2322.64 3010.63,2426.18 v1(2993.11,2426.18) 3000.98,2434.06 3000.98,2480.99 3008.86,2488.86 ; v1(3143.7,2341.54) 3168.31,2316.93 3207.68,2316.93 3237.2,2287.4 v1(3237.2,2286.42) ; 3146.65,2180.12 3182.09,2144.68 3224.41,2144.68 v1(3229.33,2139.76) ; v1(3146.65,2476.38) 3149.61,2473.43 v1(3229.33,2473.43) ; v1(3213.58,2085.63) 3189.96,2062.01 3189.96,2013.09 3196.54,2006.51 3642.34,2006.51 v1(3669.29,2033.46) ; 3258.86,2254.92 3258.86,2258.86 3262.8,2262.8 v1(3262.8,2276.57) ; v1(3684.06,3239.17) 3710.63,3212.6 3779.31,3212.6 3924.98,3066.93 4159.01,3066.93 4181.65,3044.29 4243.08,3044.29 4262.77,3063.98 4290.35,3063.98 v1(4292.32,3062.01) ; v1(3770.73,1609.63) 3770.02,1608.92 3782.48,1596.46 v1(3884.84,1596.46) 4226.95,1596.46 4431.68,1801.18 v1(4448.82,1801.18) 4448.82,1812.6 4457.68,1821.46 4457.68,1836.42 4430.45,1863.65 4423.76,1863.65 v1(4411.42,1875.98) ; v1(3823.82,3320.87) 3813.98,3330.71 3802.17,3330.71 ; v1(3825.79,3255.91) 3849.04,3255.91 3959.28,3145.67 4197.83,3145.67 4206.69,3154.53 v1(4210.63,3154.53) 4222.44,3142.72 ; v1(3863.37,1744.28) 3861.22,1744.09 4187.99,1744.09 4332.87,1888.98 4373.23,1888.98 4386.22,1875.98 ; 4125.98,153.74 4134.06,145.67 4165.16,145.67 4173.23,153.74 4173.23,207.68 4189.96,224.41 v1@4218.5,224.41 ; 4163.39,269.68 4354.33,269.68 4393.7,230.31 v1(4393.7,201.77) 4379.92,187.99 4348.43,187.99 ; v1(4203.74,1518.7) 4238.19,1518.7 4401.57,1682.09 v1(4414.37,1682.09) ; v1(4383.86,2570.87) 4348.43,2570.87 ; v1(4487.2,2554.13) 4640.16,2554.13 4661.61,2532.68 4641.73,2512.8 ; v1(4558.07,702.76) 4572.83,687.99 4595.47,687.99 4618.11,710.63 ; 532.48,2904.53 484.45,2904.53 134.84,2554.92 134.84,1607.28 689.96,1052.17 v1(873.03,1052.17) 903.54,1021.65 973.23,1021.65 981.3,1029.73 981.3,1041.14 907.28,1115.16 650.59,1115.16 150.59,1615.16 150.59,2532.79 413.08,2795.28 423.23,2795.28 532.48,2904.53 ; 2644.69,3304.92 2652.76,3312.99 2662.4,3312.99 ; 2644.69,3304.92 2644.69,3247.72 2657.48,3234.93 2657.48,3122.05 2682.09,3097.44 2794.97,3097.44 2924.89,2967.52 3149.61,2967.52 3216.54,2900.59 3260.83,2900.59 v1(3260.83,2905.51) 3260.83,2916.34 3186.02,2991.14 2936.02,2991.14 2806.1,3121.06 2740.16,3121.06 2681.1,3180.12 2681.1,3294.29 2662.4,3312.99 ; 2662.4,3312.99 2678.15,3312.99 ; 3785.43,3313.98 3802.17,3330.71 ; 3785.43,3313.98 3752.17,3313.98 3731.3,3293.11 3731.3,3248.03 3741.14,3238.19 3788.81,3238.19 3936.45,3090.55 4169.04,3090.55 4191.68,3067.91 4230.12,3067.91 4257.68,3095.47 ; 3785.43,3313.98 3764.76,3293.31 3764.76,3262.99 3773.82,3253.94 3795.33,3253.94 3942.97,3106.3 4175.56,3106.3 4186.39,3095.47 4257.68,3095.47 ; 3802.17,3330.71 3802.17,3280.51 3952.76,3129.92 4190.94,3129.92 4201.77,3119.09 4213.58,3119.09 4222.44,3127.95 4222.44,3142.72 ; v1@4218.5,224.41 4210.63,216.54 4210.63,153.54 4220.47,143.7 4220.47,65.94 4214.57,60.04 4214.57,45.47 4222.64,37.4 4234.05,37.4 4242.13,45.47 4242.13,161.42 4219.49,184.06 v1@4219.49,224.41 ; v1@4218.5,224.41 v1(4219.49,225.39) v1@4219.49,224.41 ; v1@4219.49,224.41 4223.43,228.35 4250,228.35 ; 4222.44,3142.72 4242.91,3142.72 4266.73,3118.9 4266.73,3104.53 4257.68,3095.47 ; 4250,228.35 4229.33,207.68 4229.33,196.06 4244.29,181.1 4285.12,181.1 4306.1,160.12 4306.1,77.76 4286.42,58.07 4286.42,45.47 4294.49,37.4 4325.59,37.4 4333.66,45.47 4333.66,60.04 4329.72,63.98 4329.72,181.1 4336.61,187.99 4348.43,187.99 ; 4250,228.35 4308.07,228.35 4348.43,187.99 ; 4348.43,2570.87 4124.02,2570.87 4093.5,2601.38 3470.78,2601.38 3305.43,2766.73 2854.33,2766.73 2650.59,2970.47 1057.76,2970.47 1021.34,2934.06 989.37,2934.06 981.3,2942.13 981.3,2953.54 1013.98,2986.22 2657.48,2986.22 2861.22,2782.48 3319.21,2782.48 3465.86,2635.83 4283.46,2635.83 4348.43,2570.87 ; 4386.22,1875.98 v1(4411.42,1875.98) ; 4386.22,1875.98 4372.05,1861.81 4372.05,1851.07 4221.77,1700.79 v1(3886.81,1700.79) 3886.81,1700 3883.66,1696.85 3869.29,1696.85 3859.25,1686.81 3859.25,1656.69 3869.75,1646.2 3881.36,1646.2 v1(3886.81,1640.75) 3886.81,1637.8 4214.57,1637.8 v1(4382.87,1806.1) 4392.75,1815.98 4396.49,1815.98 4411.42,1830.91 v1(4411.42,1875.98) ; 5175.39,818.9 5186.81,818.9 5194.88,810.83 5194.88,720.47 ; 5175.39,818.9 5175.39,836.61 5207.88,869.09 5219.29,869.09 5227.36,861.02 5227.36,726.58 5219.29,718.5 5196.85,718.5 5194.88,720.47 ; 5175.39,818.9 5162.4,805.9 v1(5162.4,794.29) 5162.4,585.63 5170.28,577.76 5187.01,577.76 5194.88,585.63 5194.88,720.47
  Bottom w4.72: 2865.16,2077.76 2890.26,2077.76 3648.72,1319.29 3659.06,1319.29 3668.31,1310.04 3699.18,1310.04 3709.06,1319.92 3709.06,1331.66 3673.59,1367.13 v1(3683.07,1364.17)
  Bottom w5.91: 2865.16,2077.76 2806.88,2077.76 2797.24,2087.39 2797.24,2102.76 2817.32,2122.83 2884.91,2122.83 2898.61,2109.14 2907.59,2109.14 v1(2915.35,2101.38) ; v1(2985.24,2180.12) 2985.24,2200.83 2967.56,2218.5 2953.7,2218.5 2938.98,2203.78 v1(2938.98,2186.02) ; v1@3041.34,2190.94 v1(3042.32,2191.93) ; 4255.81,1416.34 4230.31,1416.34 ; v1(2938.98,2186.02) 2904.32,2186.02 2892.72,2174.42 2892.72,2152.35 2910.22,2134.84 2938.43,2134.84 3215.99,1857.28 3327.32,1857.28 3530.51,1654.09 3530.51,1627.41 3744.53,1413.39 3782.48,1413.39 3820.87,1375 4235.24,1375 4239.17,1378.94 4239.17,1407.48 4230.31,1416.34 ; v1(2938.98,2186.02) 2938.98,2182.52 3228.78,1892.72 3371.05,1892.72 3847.43,1416.34 4230.31,1416.34
  Bottom w7.87: v1(4597.44,2459.65) 4645.92,2459.65 4653.8,2451.77 4693.53,2451.77 4702.76,2461 4702.76,2474.04 4683.93,2492.87 4674.45,2492.87 v1(4658.46,2508.86) ; 5131.89,818.9 5131.89,533.46 v1(5134.84,530.51)
  Bottom w9.84: v1(2184.06,312.01) 2184.06,571.85 2062.01,693.9 2062.01,809.06 2116.14,863.19 2627.95,863.19 v1(2738.19,752.95) ; 2788.39,2069.88 2820.87,2037.4 2891.18,2037.4 3591.54,1337.05 3591.54,1292.32 v1(3613.19,1284.45) ; v1@2798.23,2365.16 v1(2893.7,2365.16) ; v1(2817.91,2649.61) 2800.2,2631.89 2800.2,2591.49 2852.32,2539.37 3019.08,2539.37 3031.87,2534.45 3031.5,2533.46 v1(3040.35,2523.62) 3040.85,2524.11 3041.34,2523.62 3041.34,2494.64 3164.92,2371.06 3223.43,2371.06 v1(3256.89,2337.6) ; v1(2850.39,2651.57) 3181.1,2651.57 ; 2940.94,2441.97 2955.71,2427.21 2955.71,2371.06 3146.65,2180.12 ; v1(2942.91,2607.28) 3088.58,2607.28 v1(3131.89,2563.98)
  Bottom w11.81: v1(4558.07,702.76) 4541.87,702.76 4526.57,718.06 4526.57,825.25 4544.83,843.5 4637.71,843.5 4958.58,1164.37 5085.09,1164.37 5108.27,1141.2 5108.27,1089.12 5085.09,1065.94 4944.6,1065.94 4629.64,750.98 v1(4622.05,750.98)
